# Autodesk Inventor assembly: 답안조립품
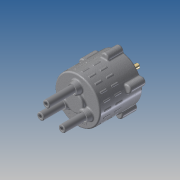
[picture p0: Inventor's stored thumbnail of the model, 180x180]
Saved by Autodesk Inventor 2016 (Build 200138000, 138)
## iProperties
Created: 2016-01
Part Number: 답안조립품
Document SubType Name: Assembly
Designer: Administrator
Author: Administrator
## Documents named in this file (14)
- D:\360106V1035\360106V1035\답안조립품.iam
- D:\360106V1035\360106V1035\본체.ipt
- D:\360106V1035\360106V1035\M5x0.8x20.ipt
- D:\360106V1035\360106V1035\멈춤링 10 x 1.ipt
- D:\360106V1035\360106V1035\멈춤링 22 x 1.2.ipt
- D:\360106V1035\360106V1035\메인 축.ipt
- D:\360106V1035\360106V1035\베어링 NA 4900.ipt
- D:\360106V1035\360106V1035\스프링1.ipt
- D:\360106V1035\360106V1035\스프링2.ipt
- D:\360106V1035\360106V1035\스프링3.ipt
- D:\360106V1035\360106V1035\슬라이드 축.ipt
- D:\360106V1035\360106V1035\오일실.ipt
- D:\360106V1035\360106V1035\커버.ipt
- D:\360106V1035\360106V1035\판캠.ipt
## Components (5 placed, 1 different names)
1. M5x0.8x20:1
2. M5x0.8x20:2
3. M5x0.8x20:3
4. M5x0.8x20:4
5. M5x0.8x20:5
